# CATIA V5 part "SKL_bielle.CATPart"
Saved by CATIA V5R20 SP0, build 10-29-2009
Part number: SKL_bielle
Publications: "Axe_D_bielle", "Axe_C_bielle", "Segment_CD", "D", "C", "Plan_Ref", "B", "Segment_CB", "Axe_B_bielle", "Plan_Ter", "Plan_Sec"
Bounding box of the stored display mesh (mm): x -5 to 5, y 9.366 to 26.656, z 2.77 to 5.779
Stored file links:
  C:\Users\MATT\Desktop\CATIA_Projet_IAO\CATIA FINAL\SKL_bielle.CATPart
  C:\Users\MATT\Desktop\CATIA_Projet_IAO\CATIA FINAL\SKL_Parametre_Projet_IAO.CATProduct
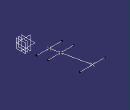
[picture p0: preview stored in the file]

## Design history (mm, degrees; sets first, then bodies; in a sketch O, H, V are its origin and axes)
External parameters (linked from other documents)
  External.AC = 3 mm
  `External.Paramètre1` = 5.85 mm
  External.CoeffAC = 3
Set1
  Plane1 "Plan_Ref": type Offset, RefPlane Plane4, Offset 0
  Point1 "C": (0, 0, 0), relative to Sketch1.P3
  Point2 "D": (0, 0, 0), relative to Sketch2.P3
  Line1 "Segment_CD": type PtPt, FirstPoint Point1, SecondPoint Point2
  Line2 "Axe_C_bielle": type Normal, RefPoint Point1, RefSkin Plane1, Start -5, End 5
  Line3 "Axe_D_bielle": type Normal, RefPoint Point2, RefSkin Plane1, Start -5, End 5
  Point3 "B": (0, 0, 0), relative to Point5
  Sketch1 on Plane1, origin (0, 0, 0), H (0, 1, 0), V (0, 0, 1)
    circle A1 centre (12, 5.85) radius 3
    point P1 (12, 5.85)
    circle A2 centre (26.6557, 5.779) radius 12.9
    point P2 (26.6557, 5.779)
    reference projected point E1 (26.6557, 5.779) from Point3
    reference projected point E2 (12, 5.85) from Point6
    point P3 (13.9467, 3.5674)
    radius A2 = 12.9 {= 4.3*External.AC}
    radius A1 = 3 {= External.AC}
    coincidence: P2 E1, P1 E2, P3 A2, P3 A1
  Sketch2 on Plane1, origin (0, 0, 0), H (0, 1, 0), V (0, 0, 1)
    circle A1 centre (26.6557, 5.779) radius 17.55
    point P1 (26.6557, 5.779)
    reference projected point E1 (26.6557, 5.779) from Point3
    circle A2 centre (13.9467, 3.5674) radius 4.65
    point P2 (13.9467, 3.5674)
    reference projected point E2 (13.9467, 3.5674) from Point1
    point P3 (9.3656, 2.7702)
    radius A1 = 17.55 {= `External.Paramètre1` *External.CoeffAC}
    radius A2 = 4.65 {= (`External.Paramètre1`*External.CoeffAC ) - (4.3mm*External.CoeffAC )}
    coincidence: P1 E1, P2 E2, P3 A1, P3 A2
  Line4 "Segment_CB": type PtPt, FirstPoint Point1, SecondPoint Point3
  Line5 "Axe_B_bielle": type Normal, RefPoint Point3, RefSkin Plane1, Start -5, End 5
  Plane2 "Plan_Sec": type Offset, RefPlane Plane5, Offset 0
  Plane3 "Plan_Ter": type Offset, RefPlane Plane6, Offset 0
Set2
  Plane4 "Plan_Ref": linked copy from another document
  Point4 "F": linked copy from another document
  Point5 "B": linked copy from another document
  Point6 "A": linked copy from another document
  Plane5 "Plan_Sec": linked copy from another document
  Plane6 "Plan_Ter": linked copy from another document
Body1 (main body)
